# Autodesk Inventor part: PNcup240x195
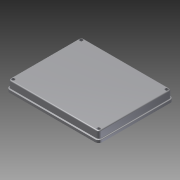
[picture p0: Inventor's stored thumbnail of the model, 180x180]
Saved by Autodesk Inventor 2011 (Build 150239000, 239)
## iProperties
Created: 2015-01
Part Number: PNcup240x195
Document SubType Name: Modeling
Designer: Evgeny
Density: 1 g/cm^3
Mass: 128.635 g
Surface Area: 1424.84 cm^2
Volume: 128.635 cm^3
Author: Evgeny
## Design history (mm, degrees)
sketch "Эскиз1"
  geometry: L1 (-115, 1)-(-115, 6); L2 (-118, 7)-(-119, 7); L3 (-120, 6)-(-120, 0); L4 (-117, 8)-(-117, 24); L5 (-117, 24)-(-115, 24); L6 (-115, 24)-(-115, 6); L7 (-118.3, 0)-(-118.3, 5); L8 (-118.3, 5)-(-116, 5); L9 (-116, 5)-(-116, 1); L10 (-120, 0)-(-118.3, 0); L11 (-116, 1)-(-115, 1); A1 r 1 centre (-118, 8) between (-118, 7) and (-117, 8); A2 r 1 centre (-119, 6) between (-119, 7) and (-120, 6); 2 further points
  constraints: 22 end point, 6 parallel, 4 point on circle, 4 tangent, 2 centre point, 2 horizontal, 2 perpendicular, 1 coincident, 1 equal radius, 1 horizontal alignment
  dimensions: "d0" = 5 distance between parallel lines of L1 L3; "d1" = 1.7 distance between parallel lines of L7 L3; "d2" = 2.3 distance between parallel lines of L7 L9; "d3" = 3 distance between parallel lines of L4 L3; "d4" = 7 distance between parallel lines of L2 L10; "d5" = 24 distance between parallel lines of L5 L10; "d6" = 5 distance between parallel lines of L8 L10; "d7" = 4 distance between parallel lines of L11 L8; "d8" = 1 radius of A1; "d9" = 115 distance from line of point (0, 0) L1; "d35" = 118.3 distance from line of point (0, 0) L7 (derived)
sketch "Эскиз2"
  geometry: L1 (110.6, 97.5)-(-110.6, 97.5); L2 (-120, 88.1)-(-120, -88.1); L3 (-110.6, -97.5)-(110.6, -97.5); L4 (120, -88.1)-(120, 88.1); A1 r 9.4 centre (110.6, 88.1) between (120, 88.1) and (110.6, 97.5); A2 r 9.4 centre (110.6, -88.1) between (110.6, -97.5) and (120, -88.1); A3 r 9.4 centre (-110.6, -88.1) between (-120, -88.1) and (-110.6, -97.5); A4 r 9.4 centre (-110.6, 88.1) between (-110.6, 97.5) and (-120, 88.1); 1 further point
  constraints: 8 end point, 8 point on circle, 8 tangent, 4 centre point, 3 equal radius, 2 parallel, 1 horizontal, 1 perpendicular
  dimensions: "d10" = 240 distance between parallel lines of L2 L4; "d11" = 195 distance between parallel lines of L3 L1; "d12" = 120 distance from line of L4 point (0, 0); "d13" = 97.5 distance from line of point (0, 0) L1; "d14" = 9.4 radius of A1
feature "Сдвиг1" sketch "Эскиз1", "Эскиз2" dims "d15" = 0
sketch "Эскиз3"
  geometry: L1 (0, 0)-(221.2, 0) reference; L2 (227.6, 6.4)-(227.6, 182.6) reference; L3 (221.2, 189)-(0, 189) reference; L4 (-6.4, 182.6)-(-6.4, 6.4) reference; A1 r 6.4 centre (0, 6.4) between (-6.4, 6.4) and (0, 0) reference; A2 r 6.4 centre (221.2, 6.4) between (221.2, 0) and (227.6, 6.4) reference; A3 r 6.4 centre (221.2, 182.6) between (227.6, 182.6) and (221.2, 189) reference; A4 r 6.4 centre (0, 182.6) between (0, 189) and (-6.4, 182.6) reference; 1 further point
extrude "Выдавливание1" join sketch "Эскиз3" distance "d16" = 1.8; taper "d17" = 0 deg
fillet "Сопряжение1" dims "d18" = 2.5
sketch "Эскиз4"
  geometry: C1 r 5 at (0, 181.6); C2 r 5 at (221.2, 181.6); C3 r 2 at (221.2, 5.4); C4 r 2 at (0, 5.4); C5 r 2 at (0, 181.6); C6 r 2 at (221.2, 181.6); C7 r 5 at (221.2, 5.4); C8 r 5 at (0, 5.4); A1 r 5.4 centre (0, 5.4) between (-5.4, 5.4) and (0, 0) reference; A2 r 5.4 centre (221.2, 5.4) between (221.2, 0) and (226.6, 5.4) reference; A3 r 5.4 centre (221.2, 181.6) between (226.6, 181.6) and (221.2, 187) reference; A4 r 5.4 centre (0, 181.6) between (0, 187) and (-5.4, 181.6) reference; 1 further point
  constraints: 8 centre point, 8 coincident
  dimensions: "d19" = 10 diameter of C1; "d20" = 10 diameter of C2; "d21" = 4 diameter of C5; "d22" = 4 diameter of C6; "d25" = 4 diameter of C3; "d26" = 4 diameter of C4; "d31" = 10 diameter of C8; "d32" = 10 diameter of C7; "d33" = 221.2 distance of C4.centre C3.centre (derived); "d34" = 176.2 distance of C2.centre C3.centre (derived)
extrude "Выдавливание3" join sketch "Эскиз4" distance "d27" = 24; taper "d28" = 0 deg
sketch "Эскиз5"
  geometry: L1 (221.2, 2.5)-(0, 2.5) reference; C1 r 3.9 at (0, 182.6); C2 r 3.9 at (221.2, 182.6); C3 r 3.9 at (0, 6.4); A1 r 3.9 centre (221.2, 6.4) between (221.2, 2.5) and (225.1, 6.4) reference; A2 r 3.9 centre (221.2, 182.6) between (225.1, 182.6) and (221.2, 186.5) reference; A3 r 3.9 centre (0, 182.6) between (0, 186.5) and (-3.9, 182.6) reference; A4 r 3.9 centre (0, 6.4) between (-3.9, 6.4) and (0, 2.5) reference; 2 further points
  constraints: 4 coincident, 3 centre point, 1 equal radius, 1 tangent, 1 vertical alignment, 3 other
extrude "Выдавливание4" cut sketch "Эскиз5" distance "d29" = 16; taper "d30" = 0 deg
fillet "Сопряжение2" dims "d36" = 0.3
node "Твердое тело1"
